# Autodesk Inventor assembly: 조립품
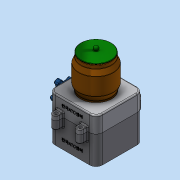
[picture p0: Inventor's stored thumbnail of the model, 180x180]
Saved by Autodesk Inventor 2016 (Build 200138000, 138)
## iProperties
Created: 2018-01
Part Number: 조립품
Material: 일반
Document SubType Name: Assembly
Designer: Administrator
Author: Administrator
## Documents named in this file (9)
- C:\Users\Administrator\Desktop\480108V1030\조립품.iam
- C:\Users\Administrator\Desktop\480108V1030\본체.ipt
- C:\Users\Administrator\Desktop\480108V1030\볼트 M4x12.ipt
- C:\Users\Administrator\Desktop\480108V1030\본체커버.ipt
- C:\Users\Administrator\Desktop\480108V1030\핸들축.ipt
- C:\Users\Administrator\Desktop\480108V1030\볼트 M3x12.ipt
- C:\Users\Administrator\Desktop\480108V1030\핸들.ipt
- C:\Users\Administrator\Desktop\480108V1030\용기.ipt
- C:\Users\Administrator\Desktop\480108V1030\용기캡.ipt
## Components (2 placed, 2 different names)
1. 핸들축:1
2. 핸들:1
